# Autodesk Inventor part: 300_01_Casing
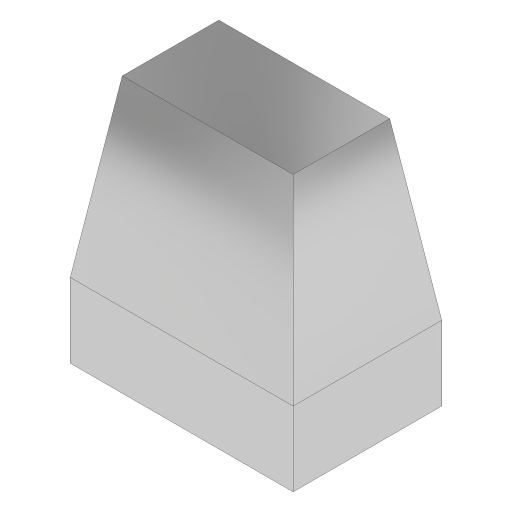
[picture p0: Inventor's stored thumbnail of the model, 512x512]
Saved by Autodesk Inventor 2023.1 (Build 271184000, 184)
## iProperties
Company: Fabian Stasiak CAD Consulting
Category: Autodesk® Inventor® Tutorial Series
Created: 2011-01
Part Number: 300_01_Casing
Material: Steel
Document SubType Name: Konstrukcja blachowa
Designer: F.Stasiak
Density: 7.85 g/cm^3
Sheet Metal Rule: Steel 2.5 mm/Round
Appearance: Chrom — polerowany
Catalog Web Link: www.expertbooks.eu
FLATAREA: =<FLAT PATTERN AREA>
Thickness: 2,500 mm
Author: F.Stasiak
Subject: Sheet Metal Design. Basic and Advanced techniques
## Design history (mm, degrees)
sketch "Szkic1"
  geometry: L1 (-150, 0)-(150, 0); L2 (150, 0)-(150, -200); L3 (150, -200)-(-150, -200); L4 (-150, -200)-(-150, 0); 2 further points
  constraints: 8 end point, 2 parallel, 1 coincident, 1 horizontal, 1 midpoint, 1 perpendicular
  dimensions: "d0" = 300 distance of L2.end L3.end; "d1" = 200 distance of L1.end L2.end
extrude "Wyciągnięcie proste1" new body sketch "Szkic1" distance "d2" = 100; taper "d3" = 0 deg
node "Płaszczyzna konstrukcyjna1"
sketch "Szkic2"
  geometry: L1 (-150, -200)-(-150, 0) reference; L2 (-150, 0)-(150, 0) reference; L3 (-150, 0)-(80, 0); L4 (80, 0)-(80, -130); L5 (80, -130)-(-150, -130); L6 (-150, -130)-(-150, 0); 1 further point
  constraints: 8 end point, 2 collinear, 2 parallel, 1 horizontal, 1 perpendicular
  dimensions: "d5" = 230 distance of L4.end L5.end; "d6" = 130 distance of L3.end L4.end
feature "Wyciągnięcie złożone1" sketch "Szkic2" dims "d7" = 0, "d8" = 90 deg, "d9" = 0, "d10" = 90 deg
  node "Krawędzie1"
node "Bryła1"
other parameters: "Thickness" = 2.5 (derived), "WspółczynnikK" = 4.4, "BendRadius" = 2.5 (= Thickness), "BendReliefWidth" = 2.5 (= Thickness), "BendReliefDepth" = 1.25 (= 0.5 x Thickness), "OdstępPołączenia" = 0.01, "MinimumRemnant" = 5 (= 2 x Thickness), "TransitionRadius" = 2.5 (= BendRadius), "JacobiRadiusSize" = 2.5 (= BendRadius), "GapSize" = 2.5 (= Thickness)
